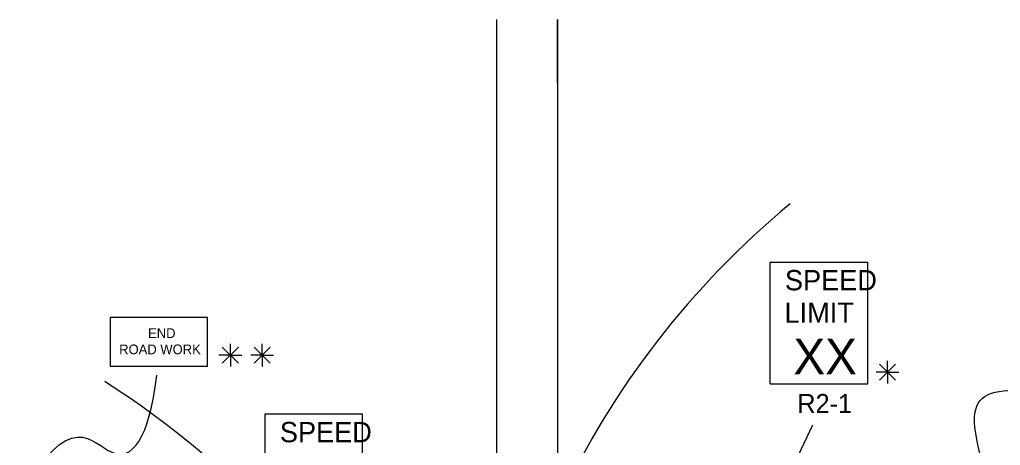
# Model space of a CAD drawing. Extents: x 16728 to 19508, y 5553 to 7079.
# Drawn here: x 16792.7 to 17179.3, y 6806.3 to 6974.1 of the extents above; entities that cross this region are included whole.
import ezdxf

# ---------------------------------------------------------------- set-up
doc = ezdxf.new("R2010")
doc.units = 0
for name, color, linetype in [('ALI_LEGAL_EX', 7, 'Continuous'), ('TRAFFIC_SIGNS_PR', 7, 'Continuous'), ('TYPICAL_TEXT_DIMEN_PR', 7, 'Continuous')]:
    doc.layers.add(name, color=color, linetype=linetype)

msp = doc.modelspace()

# ---------------------------------------------------------------- linework, layer by layer
at = {"layer": 'ALI_LEGAL_EX'}
for p, q in [((16980.68, 6974.12), (16980.68, 6155.98)), ((17004.68, 6974.12), (17004.68, 6155.98)), ((16980.68, 6877.04), (16980.68, 6013.12)), ((17004.68, 6877.04), (17004.68, 6013.12))]:
    msp.add_line(p, q, dxfattribs=at)
msp.add_lwpolyline([(17004.68, 6949.12), (17004.68, 6974.12)], dxfattribs=at)
for centre, radius, start, end in [((17313.01, 6639.38), 340, 129.5666, 180), ((16629.65, 6525.15), 364, 0, 57.2958)]:
    msp.add_arc(centre, radius, start, end, dxfattribs=at)
at = {"layer": 'TRAFFIC_SIGNS_PR'}
for p, q in [((17088.62, 6878.56), (17127.01, 6878.56)), ((17088.62, 6830.56), (17088.62, 6878.56)), ((17127.01, 6830.56), (17127.01, 6878.56)), ((17088.62, 6830.56), (17127.01, 6830.56)), ((16889.53, 6818.69), (16927.92, 6818.69)), ((16889.53, 6770.69), (16889.53, 6818.69)), ((16927.92, 6770.69), (16927.92, 6818.69))]:
    msp.add_line(p, q, dxfattribs=at)
msp.add_lwpolyline([(16828.35, 6837.49), (16866.75, 6837.49), (16866.75, 6856.69), (16828.35, 6856.69)], close=True, dxfattribs=at)
at = {"layer": 'TYPICAL_TEXT_DIMEN_PR'}
for p, q in [((16872.59, 6845.05), (16878.97, 6838.68)), ((16878.97, 6845.05), (16872.59, 6838.68)), ((16875.78, 6841.87), (16875.78, 6846.32)), ((16885.15, 6845.05), (16891.52, 6838.68)), ((16891.52, 6845.05), (16885.15, 6838.68)), ((16888.34, 6841.87), (16888.34, 6846.32)), ((16875.78, 6841.87), (16871.25, 6841.87)), ((16875.78, 6841.87), (16878.97, 6841.87)), ((16875.78, 6841.87), (16880.26, 6841.87)), ((16875.78, 6841.87), (16875.78, 6837.37)), ((16888.34, 6841.87), (16883.8, 6841.87)), ((16888.34, 6841.87), (16891.52, 6841.87)), ((16888.34, 6841.87), (16892.81, 6841.87)), ((16888.34, 6841.87), (16888.34, 6837.37)), ((17134.82, 6835.17), (17134.82, 6839.63)), ((17131.64, 6838.36), (17138.01, 6831.99)), ((17138.01, 6838.36), (17131.64, 6831.99)), ((17134.82, 6835.17), (17130.29, 6835.17)), ((17134.82, 6835.17), (17138.01, 6835.17)), ((17134.82, 6835.17), (17139.3, 6835.17)), ((17134.82, 6835.17), (17134.82, 6830.67)), ((17077.28, 6754.99), (17105.34, 6814.46))]:
    msp.add_line(p, q, dxfattribs=at)
for points in [[(16792.71, 6785.53), (16812.75, 6822.09), (16829.8, 6792), (16843.76, 6808.28), (16846.76, 6833.99)], [(17174.09, 6792.93), (17168.08, 6812.93), (17166.4, 6831.03), (17192.21, 6827.78), (17198.29, 6827.27)]]:
    msp.add_open_spline(points, degree=3, dxfattribs=at)

# ---------------------------------------------------------------- texts
at = {"layer": 'TRAFFIC_SIGNS_PR'}
for s, height, p in [('SPEED', 8, (17094.38, 6867.42)), ('LIMIT', 8, (17094.22, 6854.62)), ('END', 3.831, (16843.35, 6848.62)), ('XX', 14.031, (17097.73, 6834.32)), ('ROAD WORK', 3.831, (16831.96, 6842.23)), ('R2-1', 7.44, (17099.29, 6819.12)), ('SPEED', 8, (16895.29, 6807.55))]:
    msp.add_text(s, height=height, dxfattribs=at).set_placement(p)

doc.saveas('drawing.dxf')
